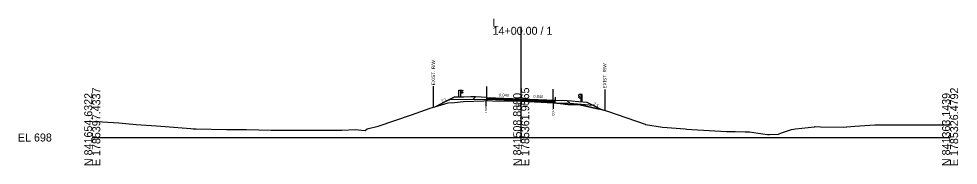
# Model space of a CAD drawing. Extents: x -26 to 5203, y -10 to 9576.
# Drawn here: x -25.7 to 302.8, y 3990.3 to 4041.6 of the extents above; entities that cross this region are included whole.
import ezdxf

# ---------------------------------------------------------------- set-up
doc = ezdxf.new("R2010")
doc.units = 0
for name, color, linetype in [('Exist Cross Section Cell', 7, 'Continuous'), ('Exist XS Center Line Elevation Label', 7, 'Continuous'), ('Exist XS Ground Line', 7, 'Continuous'), ('Old_Level_10', 7, 'Continuous'), ('Prop XS Earthwork Shape', 7, 'Continuous'), ('Prop XS EOT Tick Mark', 7, 'Continuous'), ('Prop XS Finish Grade', 7, 'Continuous'), ('Prop XS Finish Grade Earthwork', 7, 'Continuous'), ('Prop XS Finish Grade Paved Shoulder', 7, 'Continuous'), ('Prop XS Finish Grade Pavement', 7, 'Continuous'), ('Prop XS Guardrail', 7, 'Continuous'), ('Prop XS Hydro Fill Slope Data', 7, 'Continuous'), ('Prop XS Pvmt Edge Slope', 7, 'Continuous'), ('Prop XS SE Text', 7, 'Continuous'), ('Prop XS Side Slope Text', 7, 'Continuous'), ('Prop XS Subgrade Earthwork', 7, 'Continuous'), ('Scratch_Level_4', 7, 'Continuous'), ('Scratch_Level_6', 7, 'Continuous')]:
    doc.layers.add(name, color=color, linetype=linetype)

msp = doc.modelspace()

# ---------------------------------------------------------------- linework, layer by layer
at = {"layer": 'Exist Cross Section Cell'}
for p, q in [((150, 4000), (150, 4038.75)), ((0, 4000), (150, 4000)), ((150, 4000), (300, 4000))]:
    msp.add_line(p, q, dxfattribs=at)
at = {"layer": 'Exist XS Ground Line'}
msp.add_lwpolyline([(0, 4005.58), (3.56, 4005.51), (9.31, 4005.1), (15.31, 4004.53), (22.52, 4004.06), (25.53, 4003.81), (34.49, 4003.2), (35.29, 4003.09), (36.31, 4003.03), (46.96, 4002.82), (53.92, 4002.76), (62.53, 4002.56), (72.8, 4002.57), (86.93, 4002.56), (87.1, 4002.56), (87.27, 4002.57), (92.05, 4002.8), (94.19, 4002.58), (95.48, 4002.51), (96.11, 4003.01), (99.97, 4003.94), (111.65, 4007.93), (118.16, 4010.22), (121.02, 4011.14), (124.42, 4012.11), (126.69, 4012.28), (129.78, 4012.59), (136.91, 4012.89), (137.69, 4012.92), (139.95, 4012.88), (149.97, 4012.69), (150, 4012.69), (156.99, 4012.37), (161.23, 4012.14), (163.66, 4011.9), (166.33, 4011.61), (170.59, 4011.43), (176.25, 4010.16), (178.08, 4009.78), (180.21, 4009.18), (193.34, 4004.65), (193.53, 4004.6), (199.39, 4003.58), (207.3, 4002.99), (207.9, 4002.91), (209.74, 4002.85), (221.78, 4002.16), (224.82, 4002.05), (228.28, 4001.95), (229.82, 4001.94), (232.92, 4001.52), (236.16, 4001.07), (236.82, 4001.08), (240, 4001.21), (241.08, 4001.69), (244.55, 4002.79), (245.91, 4003.06), (252.62, 4003.78), (252.84, 4003.8), (254.72, 4003.79), (262.89, 4003.66), (263.76, 4003.7), (263.91, 4003.73), (266.67, 4003.93), (273.71, 4004.39), (277.9, 4004.42), (283.57, 4004.43), (285.07, 4004.44), (298.99, 4004.4), (299.26, 4004.4), (300, 4004.37)], dxfattribs=at)
at = {"layer": 'Old_Level_10'}
for p, q in [((119.25, 4017.98), (119.25, 4010.57)), ((179.25, 4016.85), (179.25, 4009.45)), ((137.69, 4012.92), (137.69, 4010.87)), ((161.15, 4012.14), (161.15, 4010.09))]:
    msp.add_line(p, q, dxfattribs=at)
at = {"layer": 'Prop XS Earthwork Shape'}
for points in [[(133.12, 4013.34), (124.77, 4013.17), (120.17, 4010.87), (121.02, 4011.14), (124.42, 4012.11), (126.69, 4012.28), (129.78, 4012.59), (136.91, 4012.89), (137.69, 4012.92), (138, 4012.91), (138, 4013.14)], [(161.96, 4012.18), (166.96, 4011.98), (175.09, 4011.33), (178.35, 4009.71), (178.08, 4009.78), (176.25, 4010.16), (170.59, 4011.43), (166.33, 4011.61), (163.66, 4011.9), (161.23, 4012.14), (161.15, 4012.14), (161.15, 4012.22)]]:
    msp.add_lwpolyline(points, close=True, dxfattribs=at)
at = {"layer": 'Prop XS EOT Tick Mark'}
for p, q in [((138, 4014.06), (138, 4015.06)), ((162, 4013.1), (162, 4014.1))]:
    msp.add_line(p, q, dxfattribs=at)
at = {"layer": 'Prop XS Finish Grade'}
for p, q in [((124.77, 4013.17), (126.57, 4014.07)), ((129.57, 4014.13), (126.57, 4014.07)), ((130, 4014.14), (129.57, 4014.13)), ((132.43, 4014.19), (130, 4014.14)), ((134, 4014.22), (132.43, 4014.19)), ((166, 4012.94), (167.61, 4012.81)), ((167.61, 4012.81), (170, 4012.62)), ((170, 4012.62), (173, 4012.38)), ((173, 4012.38), (175.09, 4011.33))]:
    msp.add_line(p, q, dxfattribs=at)
at = {"layer": 'Prop XS Finish Grade Earthwork'}
for p, q in [((124.77, 4013.17), (120.17, 4010.87)), ((175.09, 4011.33), (178.35, 4009.71))]:
    msp.add_line(p, q, dxfattribs=at)
at = {"layer": 'Prop XS Finish Grade Paved Shoulder'}
for p, q in [((138, 4014.06), (134, 4014.22)), ((162, 4013.1), (166, 4012.94))]:
    msp.add_line(p, q, dxfattribs=at)
at = {"layer": 'Prop XS Finish Grade Pavement'}
for p, q in [((138, 4014.06), (150, 4013.58)), ((150, 4013.58), (162, 4013.1))]:
    msp.add_line(p, q, dxfattribs=at)
at = {"layer": 'Prop XS Guardrail'}
for p, q in [((128.25, 4014.11), (128.25, 4016.61)), ((128.25, 4016.61), (128.75, 4016.61)), ((128.75, 4016.61), (128.75, 4014.11)), ((128.75, 4016.61), (129.25, 4016.61)), ((129.25, 4015.47), (128.75, 4015.47)), ((129.25, 4016.61), (129.54, 4016.41)), ((129.54, 4016.29), (129.25, 4016.09)), ((129.25, 4016.09), (129.25, 4015.99)), ((129.25, 4015.99), (129.54, 4015.79)), ((129.54, 4015.67), (129.25, 4015.47)), ((129.54, 4016.41), (129.57, 4016.35)), ((129.57, 4016.35), (129.54, 4016.29)), ((129.54, 4015.79), (129.57, 4015.73)), ((129.57, 4015.73), (129.54, 4015.67)), ((170.03, 4014.81), (170, 4014.75)), ((170, 4014.75), (170.03, 4014.69)), ((170.32, 4015.01), (170.03, 4014.81)), ((170.03, 4014.69), (170.32, 4014.49)), ((170.82, 4015.01), (170.32, 4015.01)), ((170.82, 4015.01), (170.82, 4012.51)), ((171.32, 4015.01), (170.82, 4015.01)), ((171.32, 4012.51), (171.32, 4015.01)), ((170.03, 4014.2), (170, 4014.14)), ((170, 4014.14), (170.03, 4014.08)), ((170.32, 4014.4), (170.03, 4014.2)), ((170.03, 4014.08), (170.32, 4013.88)), ((170.32, 4014.49), (170.32, 4014.4)), ((170.32, 4013.88), (170.82, 4013.88))]:
    msp.add_line(p, q, dxfattribs=at)
at = {"layer": 'Prop XS Hydro Fill Slope Data'}
for p, q in [((126.57, 4014.07), (120.17, 4010.87)), ((173, 4012.38), (178.35, 4009.71))]:
    msp.add_line(p, q, dxfattribs=at)
at = {"layer": 'Prop XS Pvmt Edge Slope'}
for p, q in [((134, 4014.22), (133.12, 4013.34)), ((166, 4012.94), (166.96, 4011.98))]:
    msp.add_line(p, q, dxfattribs=at)
at = {"layer": 'Prop XS Subgrade Earthwork'}
for p, q in [((133.12, 4013.34), (124.77, 4013.17)), ((138, 4013.14), (133.12, 4013.34)), ((138, 4012.91), (138, 4013.14)), ((161.15, 4012.14), (161.15, 4012.22)), ((161.15, 4012.22), (161.96, 4012.18)), ((161.96, 4012.18), (166.96, 4011.98)), ((166.96, 4011.98), (175.09, 4011.33))]:
    msp.add_line(p, q, dxfattribs=at)
at = {"layer": 'Scratch_Level_4'}
for p, q in [((138, 4012.91), (138, 4017.86)), ((161.15, 4012.14), (161.15, 4016.93)), ((138, 4013.93), (150, 4013.45)), ((150, 4013.45), (162, 4012.97))]:
    msp.add_line(p, q, dxfattribs=at)
at = {"layer": 'Scratch_Level_6'}
for p, q in [((137.98, 4013.48), (149.98, 4013)), ((150, 4013.45), (138, 4013.93)), ((138, 4013.93), (138, 4013.81)), ((138, 4013.81), (150, 4013.33)), ((138, 4013.81), (150, 4013.33)), ((150, 4013.33), (138, 4013.81)), ((138, 4013.81), (138, 4013.48)), ((138, 4013.48), (149.98, 4013)), ((149.98, 4013), (138, 4013.48)), ((138, 4013.48), (138, 4013.14)), ((138, 4013.14), (138, 4012.91)), ((149.98, 4013), (161.98, 4012.52)), ((149.98, 4013), (161.15, 4012.55)), ((161.15, 4012.55), (149.98, 4013)), ((161.15, 4013.01), (150, 4013.45)), ((150, 4013.33), (162, 4012.85)), ((150, 4013.33), (161.15, 4012.88)), ((161.15, 4012.88), (150, 4013.33)), ((161.15, 4012.88), (161.15, 4013.01)), ((161.15, 4012.55), (161.15, 4012.88)), ((161.15, 4012.22), (161.15, 4012.55)), ((161.15, 4012.14), (161.15, 4012.22))]:
    msp.add_line(p, q, dxfattribs=at)
msp.add_lwpolyline([(138, 4012.91), (139.95, 4012.88), (149.97, 4012.69), (150, 4012.69), (156.99, 4012.37), (161.15, 4012.14)], dxfattribs=at)

# ---------------------------------------------------------------- texts
at = {"layer": 'Exist Cross Section Cell'}
for s, p in [('L', (140, 4038.75)), ('14+00.00 / 1', (140, 4035.95)), ('EL 698', (-26, 3998.6))]:
    msp.add_text(s, height=2.8, dxfattribs=at).set_placement(p)
for s, p in [('N 841654.6322', (0, 3990)), ('E 1785397.4337', (2.8, 3990)), ('N 841508.8880', (150, 3990)), ('E 1785361.9565', (152.8, 3990)), ('N 841363.1439', (300, 3990)), ('E 1785326.4792', (302.8, 3990))]:
    msp.add_text(s, height=2.8, rotation=90, dxfattribs=at).set_placement(p)
at = {"layer": 'Exist XS Center Line Elevation Label'}
msp.add_text('710.69', height=1, dxfattribs=at).set_placement((147.95, 4010.69))
at = {"layer": 'Old_Level_10'}
for s, height, p in [('EXIST. R/W', 1.181, (119.84, 4018.28)), ('EXIST. R/W', 1.181, (179.84, 4017.15)), ('EOP', 0.787, (138.09, 4008.47)), ('EOP', 0.787, (161.54, 4007.69))]:
    msp.add_text(s, height=height, rotation=90, dxfattribs=at).set_placement(p)
at = {"layer": 'Prop XS SE Text'}
for p in [(142.25, 4014.39), (154.25, 4013.91)]:
    msp.add_text('0.040', height=1, rotation=357.7094, dxfattribs=at).set_placement(p)
at = {"layer": 'Prop XS Side Slope Text'}
for rotation, p in [(26.5651, (122.34, 4012.18)), (333.4349, (175.15, 4011.5))]:
    msp.add_text('2:1', height=1, rotation=rotation, dxfattribs=at).set_placement(p)

doc.saveas('drawing.dxf')
